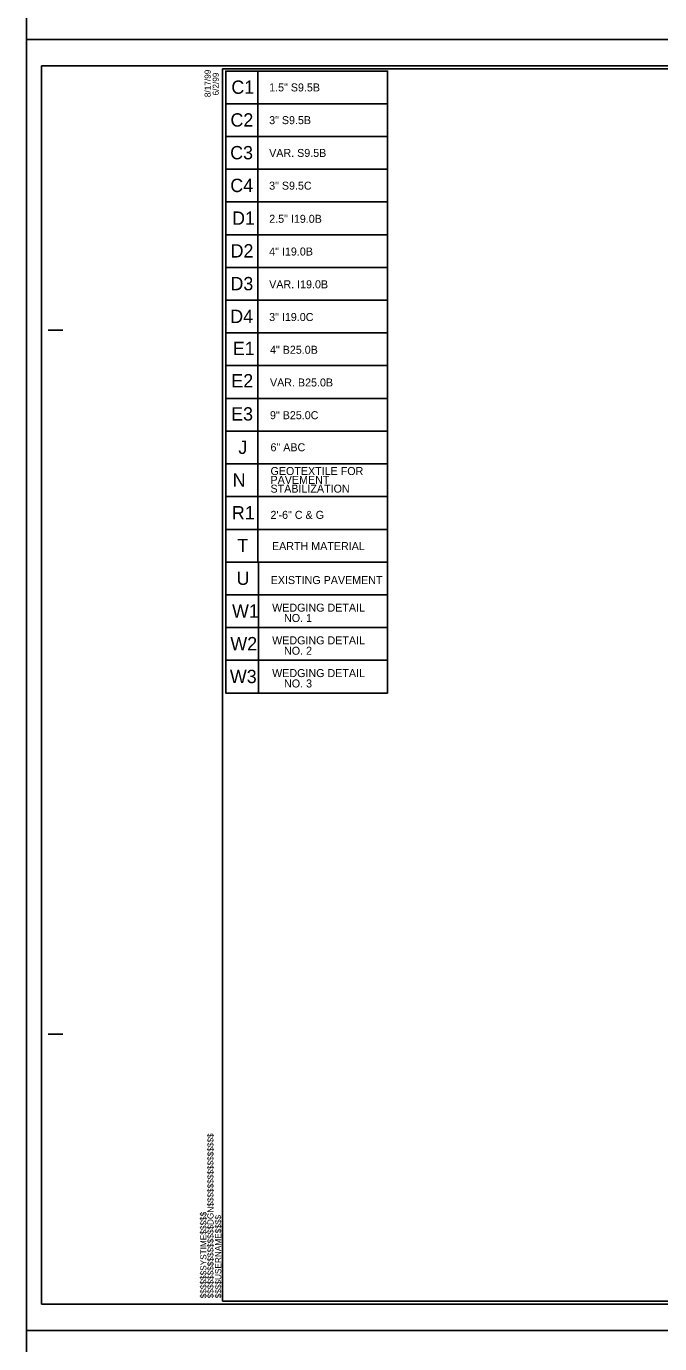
# Model space of a CAD drawing. Extents: x 573813 to 575363, y -54752 to -53123.
# Drawn here: x 574669.7 to 574777.6, y -53785.4 to -53560.8 of the extents above; entities that cross this region are included whole.
import ezdxf

# ---------------------------------------------------------------- set-up
doc = ezdxf.new("R2010")
doc.units = 0
for name, color, linetype in [('Old_Level_1', 7, 'Continuous'), ('Prop Pavement Schedule Description CELL', 7, 'Continuous'), ('Sheet Cutting Line CELL', 7, 'Continuous'), ('Sheet Plot Border Inside CELL', 7, 'Continuous'), ('Sheet Plot Border Outside CELL', 7, 'Continuous'), ('Sheet Typical CELL', 7, 'Continuous')]:
    doc.layers.add(name, color=color, linetype=linetype)

msp = doc.modelspace()

# ---------------------------------------------------------------- linework, layer by layer
at = {"layer": 'Prop Pavement Schedule Description CELL'}
for points in [[(574709.17, -53574.03), (574703.71, -53574.03), (574703.71, -53568.45), (574731.27, -53568.45), (574731.27, -53574.03), (574709.17, -53574.03), (574709.17, -53568.45)], [(574709.17, -53579.61), (574703.71, -53579.61), (574703.71, -53574.03), (574731.27, -53574.03), (574731.27, -53579.61), (574709.17, -53579.61), (574709.17, -53574.03)], [(574709.17, -53585.19), (574703.71, -53585.19), (574703.71, -53579.61), (574731.27, -53579.61), (574731.27, -53585.19), (574709.17, -53585.19), (574709.17, -53579.61)], [(574709.17, -53590.77), (574703.71, -53590.77), (574703.71, -53585.19), (574731.27, -53585.19), (574731.27, -53590.77), (574709.17, -53590.77), (574709.17, -53585.19)], [(574709.17, -53596.35), (574703.71, -53596.35), (574703.71, -53590.77), (574731.27, -53590.77), (574731.27, -53596.35), (574709.17, -53596.35), (574709.17, -53590.77)], [(574709.17, -53601.94), (574703.71, -53601.94), (574703.71, -53596.35), (574731.27, -53596.35), (574731.27, -53601.93), (574709.17, -53601.93), (574709.17, -53596.35)], [(574709.16, -53607.52), (574703.71, -53607.52), (574703.71, -53601.94), (574731.26, -53601.94), (574731.26, -53607.52), (574709.16, -53607.52), (574709.16, -53601.94)], [(574709.16, -53613.1), (574703.71, -53613.1), (574703.71, -53607.52), (574731.26, -53607.52), (574731.26, -53613.1), (574709.16, -53613.1), (574709.16, -53607.52)], [(574709.16, -53618.68), (574703.71, -53618.68), (574703.71, -53613.1), (574731.26, -53613.1), (574731.26, -53618.68), (574709.16, -53618.68), (574709.16, -53613.1)], [(574709.16, -53624.27), (574703.71, -53624.27), (574703.71, -53618.68), (574731.26, -53618.68), (574731.26, -53624.27), (574709.16, -53624.27), (574709.16, -53618.68)], [(574709.16, -53629.85), (574703.71, -53629.85), (574703.71, -53624.27), (574731.26, -53624.27), (574731.26, -53629.85), (574709.16, -53629.85), (574709.16, -53624.27)], [(574709.16, -53635.43), (574703.71, -53635.43), (574703.71, -53629.85), (574731.26, -53629.85), (574731.26, -53635.43), (574709.16, -53635.43), (574709.16, -53629.85)], [(574709.16, -53641.01), (574703.71, -53641.01), (574703.71, -53635.43), (574731.26, -53635.43), (574731.26, -53641.01), (574709.16, -53641.01), (574709.16, -53635.43)], [(574709.16, -53646.59), (574703.71, -53646.59), (574703.71, -53641.01), (574731.26, -53641.01), (574731.26, -53646.59), (574709.16, -53646.59), (574709.16, -53641.01)], [(574709.16, -53652.17), (574703.71, -53652.17), (574703.71, -53646.59), (574731.26, -53646.59), (574731.26, -53652.17), (574709.16, -53652.17), (574709.16, -53646.59)], [(574709.28, -53657.75), (574703.7, -53657.75), (574703.7, -53652.17), (574731.26, -53652.17), (574731.26, -53657.75), (574709.28, -53657.75), (574709.28, -53652.17)], [(574709.28, -53663.33), (574703.7, -53663.33), (574703.7, -53657.75), (574731.26, -53657.75), (574731.26, -53663.33), (574709.28, -53663.33), (574709.28, -53657.75)], [(574709.28, -53668.92), (574703.7, -53668.92), (574703.7, -53663.33), (574731.26, -53663.33), (574731.26, -53668.92), (574709.28, -53668.92), (574709.28, -53663.33)], [(574709.28, -53674.5), (574703.7, -53674.5), (574703.7, -53668.92), (574731.26, -53668.92), (574731.26, -53674.5), (574709.28, -53674.5), (574709.28, -53668.92)]]:
    msp.add_lwpolyline(points, dxfattribs=at)
at = {"layer": 'Sheet Cutting Line CELL'}
for p, q in [((574669.73, -53563.07), (574669.73, -53342.95)), ((575006.71, -53563.07), (574669.73, -53563.07)), ((574669.73, -53783.19), (574669.73, -53563.07)), ((574669.73, -53563.07), (575006.71, -53563.07)), ((575006.71, -53783.19), (574669.73, -53783.19)), ((574669.73, -54003.31), (574669.73, -53783.19)), ((574669.73, -53783.19), (575006.71, -53783.19))]:
    msp.add_line(p, q, dxfattribs=at)
at = {"layer": 'Sheet Plot Border Inside CELL'}
msp.add_lwpolyline([(575005.81, -53567.56), (574672.33, -53567.56), (574672.33, -53778.7), (575005.81, -53778.7)], close=True, dxfattribs=at)
at = {"layer": 'Sheet Plot Border Outside CELL'}
for p, q in [((574669.73, -53342.95), (574669.73, -53563.07)), ((574669.73, -53563.07), (575006.71, -53563.07)), ((575006.71, -53563.07), (574669.73, -53563.07)), ((574669.73, -53563.07), (574669.73, -53783.19)), ((574669.73, -53783.19), (575006.71, -53783.19)), ((575006.71, -53783.19), (574669.73, -53783.19)), ((574669.73, -53783.19), (574669.73, -54003.31))]:
    msp.add_line(p, q, dxfattribs=at)
for points in [[(575006.71, -53342.95), (574669.73, -53342.95), (574669.73, -53563.07), (575006.71, -53563.07)], [(575006.71, -53563.07), (574669.73, -53563.07), (574669.73, -53783.19), (575006.71, -53783.19)], [(575006.71, -53783.19), (574669.73, -53783.19), (574669.73, -54003.31), (575006.71, -54003.31)]]:
    msp.add_lwpolyline(points, close=True, dxfattribs=at)
at = {"layer": 'Sheet Typical CELL'}
for p, q in [((574673.43, -53612.6), (574675.93, -53612.6)), ((574673.43, -53732.66), (574675.93, -53732.66)), ((574703.15, -53778.19), (574703.15, -53778.19)), ((574703.15, -53778.19), (574703.15, -53778.19)), ((574703.15, -53778.19), (574703.15, -53778.19)), ((574703.15, -53778.19), (574703.15, -53778.19)), ((574703.15, -53778.19), (574703.15, -53778.19)), ((574703.15, -53778.19), (574703.15, -53778.19))]:
    msp.add_line(p, q, dxfattribs=at)
msp.add_lwpolyline([(575003.31, -53568.07), (574703.15, -53568.07), (574703.15, -53778.19), (575003.31, -53778.19)], close=True, dxfattribs=at)
msp.add_lwpolyline([(574710.65, -53778.19), (574710.65, -53778.19)], dxfattribs=at)

# ---------------------------------------------------------------- texts
at = {"layer": 'Old_Level_1'}
msp.add_text('C1', height=2.274, rotation=360, dxfattribs=at).set_placement((574704.66, -53572.33))
at = {"layer": 'Prop Pavement Schedule Description CELL'}
for s, height, p in [('1.5" S9.5B', 1.364, (574711.1, -53571.92)), ('C2', 2.274, (574704.51, -53577.92)), ('3" S9.5B', 1.364, (574711.1, -53577.5)), ('C3', 2.274, (574704.46, -53583.5)), ('VAR. S9.5B', 1.364, (574711.1, -53583.09)), ('C4', 2.274, (574704.48, -53589.08)), ('3" S9.5C', 1.364, (574711.1, -53588.67)), ('D1', 2.274, (574704.78, -53594.66)), ('2.5" I19.0B', 1.3644, (574711.11, -53594.32)), ('D2', 2.274, (574704.53, -53600.24)), ('4" I19.0B', 1.364, (574711.11, -53599.9)), ('D3', 2.274, (574704.51, -53605.83)), ('VAR. I19.0B', 1.3644, (574711.1, -53605.49)), ('D4', 2.274, (574704.47, -53611.41)), ('3" I19.0C', 1.364, (574711.1, -53611.07)), ('E1', 2.274, (574704.9, -53616.88)), ('4" B25.0B', 1.364, (574711.24, -53616.65)), ('E2', 2.274, (574704.66, -53622.39)), ('VAR. B25.0B', 1.3644, (574711.24, -53622.23)), ('E3', 2.274, (574704.63, -53628.04)), ('9" B25.0C', 1.364, (574711.24, -53627.81)), ('J', 2.27, (574705.85, -53633.73)), ('6" ABC', 1.364, (574711.33, -53633.28)), ('GEOTEXTILE FOR', 1.3644, (574711.33, -53637.33)), ('N', 2.27, (574704.87, -53639.32)), ('STABILIZATION', 1.3644, (574711.33, -53640.33)), ('PAVEMENT', 1.364, (574711.33, -53638.83)), ('R1', 2.274, (574704.75, -53644.9)), ('2\'-6" C & G', 1.3644, (574711.33, -53644.8)), ('T', 2.27, (574705.67, -53650.48)), ('EARTH MATERIAL', 1.3644, (574711.58, -53650.12)), ('U', 2.27, (574705.55, -53656.06)), ('EXISTING PAVEMENT', 1.3644, (574711.36, -53655.92)), ('W1', 2.274, (574704.78, -53661.64)), ('WEDGING DETAIL ', 1.3644, (574711.61, -53660.62)), ('    NO. 1', 1.364, (574711.61, -53662.39)), ('W2', 2.274, (574704.49, -53667.22)), ('WEDGING DETAIL ', 1.3644, (574711.61, -53666.2)), ('    NO. 2', 1.364, (574711.61, -53667.97)), ('W3', 2.274, (574704.41, -53672.81)), ('WEDGING DETAIL ', 1.3644, (574711.61, -53671.78)), ('    NO. 3', 1.364, (574711.61, -53673.55))]:
    msp.add_text(s, height=height, rotation=360, dxfattribs=at).set_placement(p)
at = {"layer": 'Sheet Typical CELL'}
for s, height, p in [('8/17/99', 1.051, (574701.14, -53572.9)), ('6/2/99', 1.051, (574702.52, -53572.61)), ('$$$$$$$$$$$$$$$$DGN$$$$$$$$$$$$$$$$', 1.0506, (574701.62, -53777.71)), ('$$$$$$SYSTIME$$$$$', 1.0506, (574700.41, -53777.71)), ('$$$$USERNAME$$$$', 1.0506, (574702.93, -53777.71))]:
    msp.add_text(s, height=height, rotation=90, dxfattribs=at).set_placement(p)

doc.saveas('drawing.dxf')
